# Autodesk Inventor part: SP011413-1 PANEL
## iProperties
Created: 2013-01
Part Number: SP011413-1 PANEL
Material: Polycarbonate, Clear
Document SubType Name: Modeling
Designer: Administrator
Mass: 5588.82 g
Surface Area: 16878.4 cm^2
Volume: 4657.35 cm^3
Density: 1.2 g/cm^3
Author: Administrator
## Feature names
1. Extrusion1
